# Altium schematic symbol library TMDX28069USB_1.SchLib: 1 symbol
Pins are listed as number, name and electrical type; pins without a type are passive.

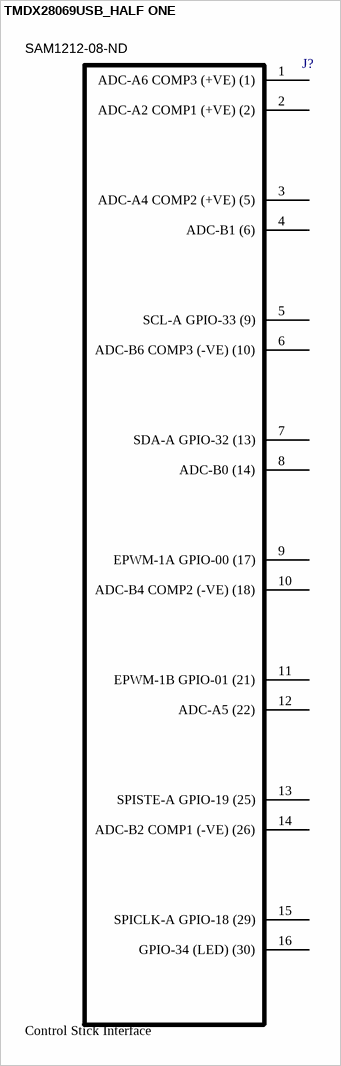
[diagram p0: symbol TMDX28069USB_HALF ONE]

## TMDX28069USB_HALF ONE
designator J?  Name: Control Stick Interface  Supplier Part Number: SAM1212-08-ND  (hidden comment: *)
DEV STICK USB PICCOLO F28069 HALF PART; PartNumber: SSW-108-01-T-D; Description: SOCKET FOR PICCOLO F28069; Board Type: Evaluation Platform; Contents: Board(s)
footprint Samtec_SSW-108-01-x-D (Receptacle, 2.54mm, 8x2, TH)
pins: 1 ADC-A6 COMP3 (+VE) (1), 2 ADC-A2 COMP1 (+VE) (2), 3 ADC-A4 COMP2 (+VE) (5), 4 ADC-B1 (6), 5 SCL-A GPIO-33 (9), 6 ADC-B6 COMP3 (-VE) (10), 7 SDA-A GPIO-32 (13), 8 ADC-B0 (14), 9 EPWM-1A GPIO-00 (17), 10 ADC-B4 COMP2 (-VE) (18), 11 EPWM-1B GPIO-01 (21), 12 ADC-A5 (22), 13 SPISTE-A GPIO-19 (25), 14 ADC-B2 COMP1 (-VE) (26), 15 SPICLK-A GPIO-18 (29), 16 GPIO-34 (LED) (30)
